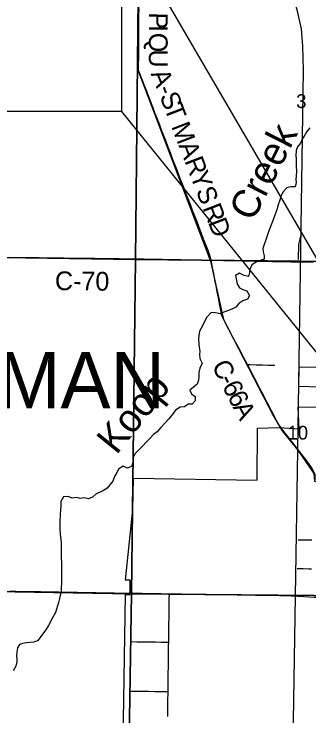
# Model space of a CAD drawing. Extents: x 0 to 34, y 0 to 22.
# Drawn here: x 4.43 to 5.324, y 17.068 to 19.194 of the extents above; entities that cross this region are included whole.
import ezdxf

# ---------------------------------------------------------------- set-up
doc = ezdxf.new("R2010")
doc.units = 0
for name, color, linetype in [('GM_X_City_Street', 7, 'Continuous'), ('GM_X_Corporation', 7, 'Continuous'), ('GM_X_County_Road', 7, 'Continuous'), ('GM_X_County_Road_Text', 7, 'Continuous'), ('GM_X_Minor_River', 7, 'Continuous'), ('GM_X_Minor_River_Text', 7, 'Continuous'), ('GM_X_Rail_Line', 7, 'Continuous'), ('GM_X_Section_Text', 7, 'Continuous'), ('GM_X_State_Route', 7, 'Continuous'), ('GM_X_Township_Road', 7, 'Continuous'), ('GM_X_Township_Text', 7, 'Continuous'), ('SH_Text', 7, 'Continuous')]:
    doc.layers.add(name, color=color, linetype=linetype)

msp = doc.modelspace()

# ---------------------------------------------------------------- linework, layer by layer
at = {"layer": 'GM_X_City_Street'}
for points in [[(5.2912, 17.6018), (5.3098, 17.6015), (5.325, 17.6013), (5.332, 17.6012)], [(5.288, 17.5145), (5.3067, 17.5143), (5.3233, 17.514), (5.3311, 17.5139)], [(4.8958, 17.0663), (4.8961, 17.085), (4.8963, 17.1036), (4.8966, 17.1223), (4.8967, 17.132), (4.8968, 17.1418), (4.8971, 17.1604), (4.8973, 17.1791), (4.8976, 17.1977), (4.8978, 17.2163), (4.8981, 17.235), (4.8983, 17.2536), (4.8985, 17.2723), (4.8987, 17.2818), (4.8988, 17.2914), (4.8991, 17.31), (4.8993, 17.3287), (4.8995, 17.3473), (4.8998, 17.366), (4.9, 17.3846), (4.9003, 17.4033), (4.9004, 17.4132), (4.9006, 17.4231), (4.9008, 17.4382)], [(4.7838, 17.2931), (4.8025, 17.2928), (4.8211, 17.2925), (4.8398, 17.2923), (4.8584, 17.292), (4.8758, 17.2917), (4.8931, 17.2915), (4.8988, 17.2914)], [(4.7819, 17.1435), (4.8005, 17.1432), (4.8191, 17.1429), (4.8378, 17.1426), (4.8564, 17.1424), (4.8724, 17.1421), (4.8884, 17.1419), (4.8968, 17.1418)]]:
    msp.add_lwpolyline(points, dxfattribs=at)
at = {"layer": 'GM_X_Corporation'}
for points in [[(4.7562, 19.4462), (4.7881, 19.4457), (4.8082, 19.4446), (4.7982, 18.4503), (3.7969, 18.4658), (3.7979, 18.8986)], [(5.3571, 18.0637), (5.2933, 18.0661), (5.2945, 18.1254), (5.6481, 18.1185)], [(4.7597, 16.9291), (4.7677, 17.4357), (4.7819, 17.4354), (4.7818, 17.4793), (4.7676, 17.4795), (4.7903, 17.6936), (4.7921, 17.7885), (5.1664, 17.7823), (5.168, 17.9398), (5.2337, 17.9415), (5.2939, 17.9379), (5.2911, 18.0031), (5.3565, 18.004)]]:
    msp.add_lwpolyline(points, dxfattribs=at)
for points in [[(5.8008, 19.4289), (5.7966, 18.4409), (4.7982, 18.4503), (4.8082, 19.4446)], [(3.7969, 18.4658), (4.7982, 18.4503), (4.7862, 17.4375), (3.785, 17.4549)], [(5.7966, 18.4409), (5.7831, 17.4286), (4.7862, 17.4375), (4.7982, 18.4503)], [(4.7862, 17.4375), (4.7695, 16.4317), (3.7672, 16.4521), (3.785, 17.4549)], [(4.7862, 17.4375), (5.7831, 17.4286), (5.7675, 16.4186), (4.7695, 16.4317)]]:
    msp.add_lwpolyline(points, close=True, dxfattribs=at)
at = {"layer": 'GM_X_County_Road'}
for points in [[(5.0579, 18.2907), (5.0565, 18.2978), (5.0529, 18.3161), (5.0494, 18.3344), (5.0458, 18.3527), (5.0422, 18.371), (5.0386, 18.3893), (5.0351, 18.4076), (5.0315, 18.4259), (5.0293, 18.4371), (5.0271, 18.4484), (5.0248, 18.46), (5.0181, 18.4774), (5.0114, 18.4948), (5.0047, 18.5122), (4.998, 18.5296), (4.9913, 18.547), (4.9846, 18.5644), (4.9779, 18.5818), (4.9712, 18.5992), (4.9645, 18.6166), (4.9578, 18.634), (4.9511, 18.6514), (4.9443, 18.6688), (4.9376, 18.6861), (4.9309, 18.7035), (4.9242, 18.7209), (4.9175, 18.7383), (4.9108, 18.7557), (4.9041, 18.7731), (4.8974, 18.7905), (4.8907, 18.8079), (4.884, 18.8253), (4.8773, 18.8427), (4.8706, 18.8601), (4.8639, 18.8775), (4.8572, 18.8949), (4.8505, 18.9122), (4.8438, 18.9296), (4.8384, 18.9435), (4.8331, 18.9574), (4.8264, 18.9748), (4.8197, 18.9922), (4.8137, 19.0079), (4.8077, 19.0236), (4.8078, 19.0422), (4.8079, 19.0609), (4.808, 19.0795), (4.8082, 19.0981), (4.8083, 19.1168), (4.8084, 19.1354), (4.8085, 19.1541), (4.8087, 19.1727), (4.8088, 19.1913), (4.8089, 19.21)], [(4.4131, 18.4573), (4.4317, 18.457), (4.4504, 18.4568), (4.469, 18.4566), (4.4876, 18.4564), (4.5063, 18.4561), (4.5249, 18.4559), (4.5436, 18.4557), (4.5622, 18.4555), (4.5808, 18.4552), (4.5995, 18.455), (4.6181, 18.4548), (4.6368, 18.4546), (4.6554, 18.4543), (4.6741, 18.4541), (4.6927, 18.4539), (4.7113, 18.4537), (4.73, 18.4534), (4.7486, 18.4532), (4.7673, 18.453), (4.7859, 18.4528), (4.7954, 18.4526), (4.8049, 18.4525), (4.8235, 18.4522), (4.8421, 18.4518), (4.8608, 18.4515), (4.8794, 18.4511), (4.898, 18.4508), (4.9167, 18.4504), (4.9353, 18.4501), (4.9539, 18.4497), (4.9726, 18.4494), (4.9912, 18.4491), (5.0091, 18.4487), (5.0271, 18.4484)], [(5.0271, 18.4484), (5.0457, 18.448), (5.0644, 18.4477), (5.083, 18.4473), (5.1016, 18.447), (5.1203, 18.4466), (5.1389, 18.4463), (5.1575, 18.4459), (5.1732, 18.4457)], [(5.1732, 18.4457), (5.1762, 18.4456), (5.1948, 18.4453), (5.2134, 18.4449), (5.2321, 18.4446), (5.2507, 18.4442), (5.2693, 18.4439), (5.285, 18.4436), (5.3007, 18.4433), (5.3194, 18.4432), (5.338, 18.443)], [(5.2404, 17.9399), (5.2305, 17.9528), (5.2249, 17.964), (5.2193, 17.9752), (5.2106, 17.9917), (5.202, 18.0082), (5.1934, 18.0248), (5.1848, 18.0413), (5.1761, 18.0578), (5.1675, 18.0743), (5.1625, 18.084), (5.1574, 18.0936), (5.149, 18.1102), (5.1434, 18.1212), (5.1377, 18.1323), (5.1356, 18.1365), (5.1268, 18.1529), (5.118, 18.1693), (5.1092, 18.1858), (5.1014, 18.2004), (5.0935, 18.215), (5.0849, 18.2315), (5.0764, 18.2481), (5.0682, 18.2638), (5.0601, 18.2795), (5.0579, 18.2907)], [(5.3424, 17.7822), (5.3424, 17.798), (5.3356, 17.8137), (5.3302, 17.8221), (5.3248, 17.8305), (5.3134, 17.8453), (5.302, 17.86), (5.2961, 17.8678), (5.2901, 17.8755), (5.2787, 17.8903), (5.2673, 17.905), (5.2559, 17.9198), (5.2481, 17.9299), (5.2404, 17.9399)]]:
    msp.add_lwpolyline(points, dxfattribs=at)
at = {"layer": 'GM_X_Minor_River'}
for points in [[(5.3264, 18.8493), (5.3174, 18.8378), (5.3092, 18.8243), (5.3036, 18.8145), (5.2977, 18.8033), (5.2891, 18.7913), (5.285, 18.7808), (5.2839, 18.7656), (5.2845, 18.7561), (5.285, 18.7435), (5.2855, 18.7325), (5.2859, 18.7177), (5.2845, 18.704), (5.2842, 18.693), (5.2848, 18.6835), (5.2822, 18.6703), (5.2693, 18.6702), (5.2571, 18.6678), (5.2443, 18.654), (5.2387, 18.6409), (5.2354, 18.6299), (5.2309, 18.6163), (5.226, 18.6005), (5.2199, 18.5843), (5.2159, 18.5741), (5.2111, 18.5609), (5.2059, 18.5478), (5.201, 18.5338), (5.1961, 18.5195), (5.1929, 18.5097)], [(5.1929, 18.5097), (5.188, 18.4961), (5.1843, 18.484), (5.1849, 18.4741), (5.1876, 18.4615), (5.1882, 18.452), (5.1759, 18.4477), (5.1637, 18.4423), (5.151, 18.4342), (5.1446, 18.4207), (5.144, 18.4108), (5.1407, 18.3987), (5.1279, 18.4017), (5.1136, 18.4092), (5.101, 18.4023), (5.1065, 18.3771), (5.1134, 18.3644), (5.1231, 18.3596), (5.1352, 18.3559), (5.1436, 18.3417), (5.138, 18.33), (5.1231, 18.3254), (5.1108, 18.3169), (5.1018, 18.3057), (5.0922, 18.3006), (5.0796, 18.2964), (5.0655, 18.291), (5.0544, 18.2863), (5.0408, 18.2889), (5.0275, 18.29), (5.0147, 18.2758), (5.008, 18.2646), (5, 18.2476), (4.9925, 18.2337), (4.9896, 18.2201), (4.9893, 18.2091), (4.9901, 18.1942), (4.9914, 18.1847), (4.9934, 18.1725), (4.9925, 18.163), (4.9933, 18.1504), (5.0002, 18.1362), (4.9931, 18.1212), (4.9901, 18.1079), (4.9898, 18.095), (4.9892, 18.0855), (4.9848, 18.0734), (4.9744, 18.0638), (4.9628, 18.0549), (4.9682, 18.0438), (4.9794, 18.0355), (4.9791, 18.0222), (4.9698, 18.0122), (4.9573, 18.0125), (4.9469, 18.0047), (4.9336, 18.0035), (4.9197, 17.9939), (4.9088, 17.9805), (4.8983, 17.9666), (4.8882, 17.9558), (4.8746, 17.9421), (4.8637, 17.929), (4.8532, 17.9201), (4.8424, 17.9097), (4.8315, 17.8986), (4.8191, 17.8855), (4.8086, 17.8744), (4.7974, 17.8625), (4.7914, 17.8508), (4.7904, 17.8375), (4.7867, 17.825), (4.7736, 17.8185), (4.7605, 17.8241), (4.7482, 17.8168), (4.7419, 17.8051), (4.7348, 17.7931), (4.7292, 17.7796), (4.7206, 17.7683), (4.7128, 17.7583), (4.7012, 17.7513), (4.6909, 17.7454), (4.679, 17.7412), (4.6678, 17.7311), (4.6555, 17.7257), (4.6423, 17.7291), (4.6309, 17.7263), (4.6204, 17.7299), (4.6067, 17.728), (4.5942, 17.7328), (4.5798, 17.7316), (4.5719, 17.7174), (4.572, 17.7056), (4.5713, 17.6919), (4.5695, 17.6782), (4.5691, 17.6577), (4.5685, 17.6463), (4.5686, 17.6334), (4.5698, 17.6189), (4.5711, 17.6093), (4.573, 17.5944), (4.5731, 17.58)], [(4.5731, 17.58), (4.5725, 17.5686), (4.5726, 17.556), (4.5731, 17.5465), (4.5739, 17.5316), (4.574, 17.5172), (4.5741, 17.5061), (4.5743, 17.4947), (4.5737, 17.4677), (4.5731, 17.4578), (4.5725, 17.4472), (4.5707, 17.4373), (4.5682, 17.4241), (4.5645, 17.4112), (4.5555, 17.3818), (4.5472, 17.3652), (4.5349, 17.3419), (4.527, 17.3292), (4.5169, 17.3157), (4.5095, 17.306), (4.5009, 17.2959), (4.489, 17.2916), (4.4795, 17.2903), (4.4681, 17.289), (4.4563, 17.2874), (4.4468, 17.2842), (4.4412, 17.2745), (4.4383, 17.2623), (4.4381, 17.2506), (4.439, 17.241), (4.4384, 17.2315), (4.4358, 17.2183), (4.428, 17.2051)]]:
    msp.add_lwpolyline(points, dxfattribs=at)
at = {"layer": 'GM_X_Rail_Line'}
msp.add_line((5.2889, 17.8736), (5.2896, 17.8726), dxfattribs=at)
for points in [[(4.7739, 20.9), (4.6919, 20.1583), (4.6938, 20.1236), (4.7468, 19.7618), (4.8037, 19.4528), (4.8092, 19.4143), (4.8049, 19.0246), (5.0256, 18.4453), (5.0645, 18.2691), (5.215, 17.9781), (5.2422, 17.9318), (5.2889, 17.8736)], [(5.2312, 14.404), (5.2346, 14.4124), (5.2368, 14.4226), (5.243, 14.9028), (5.2517, 15.4121), (5.2672, 16.4237), (5.283, 17.4313), (5.2899, 17.8728), (5.3076, 19.0241), (5.3057, 19.0962), (5.3011, 19.1491), (5.2883, 19.2066), (5.0953, 19.84), (5.0724, 19.9157), (5.0587, 19.9632), (5.0513, 20.0198), (5.0584, 20.4524), (5.0684, 20.9)], [(5.2919, 18.4509), (5.2932, 18.4955), (5.2963, 18.5082), (5.2999, 18.5253)], [(5.2896, 17.8726), (5.3382, 17.8025), (5.341, 17.7796), (5.4725, 17.777), (5.4714, 17.6262), (5.4707, 17.4295), (5.6005, 17.4236), (5.6403, 16.9891), (5.6877, 16.4369), (5.6901, 16.3801), (5.6782, 16.0923), (5.6866, 15.9567), (5.7169, 15.8341), (5.7394, 15.7967)]]:
    msp.add_lwpolyline(points, dxfattribs=at)
at = {"layer": 'GM_X_State_Route'}
msp.add_line((4.7868, 17.4398), (4.8003, 17.4396), dxfattribs=at)
for points in [[(4.417, 17.446), (4.4356, 17.4457), (4.4543, 17.4454), (4.4729, 17.4451), (4.4916, 17.4448), (4.5102, 17.4445), (4.5288, 17.4442), (4.5475, 17.4439), (4.5661, 17.4435), (4.5785, 17.4433)], [(4.5785, 17.4433), (4.5848, 17.4432), (4.6034, 17.4429), (4.622, 17.4426), (4.6407, 17.4423), (4.6593, 17.442), (4.678, 17.4417), (4.6966, 17.4413), (4.7152, 17.441), (4.7339, 17.4407), (4.7525, 17.4404), (4.7692, 17.4401), (4.7858, 17.4398), (4.7868, 17.4398)], [(4.8003, 17.4396), (4.8189, 17.4394), (4.8376, 17.4391), (4.8562, 17.4388), (4.8748, 17.4385), (4.8878, 17.4383), (4.9008, 17.4382), (4.9194, 17.4379), (4.938, 17.4376), (4.9567, 17.4373), (4.9753, 17.4371), (4.994, 17.4368), (5.0087, 17.4366)], [(5.0087, 17.4366), (5.0126, 17.4365), (5.0312, 17.4362), (5.0499, 17.436), (5.0685, 17.4357), (5.0872, 17.4354), (5.1058, 17.4351), (5.1244, 17.4349), (5.1431, 17.4346), (5.1617, 17.4343), (5.1804, 17.4341), (5.199, 17.4338), (5.2177, 17.4335), (5.2352, 17.4333), (5.2527, 17.433), (5.2713, 17.4319), (5.2899, 17.4309), (5.2987, 17.4304)], [(5.2987, 17.4304), (5.3085, 17.4298), (5.3236, 17.429), (5.3388, 17.4281), (5.3574, 17.4279), (5.3761, 17.4277), (5.3905, 17.4275), (5.4049, 17.4273)]]:
    msp.add_lwpolyline(points, dxfattribs=at)
at = {"layer": 'GM_X_Township_Road'}
msp.add_lwpolyline([(5.1377, 18.1323), (5.1456, 18.1321), (5.1642, 18.1317), (5.1828, 18.1312), (5.1992, 18.1308), (5.2155, 18.1305), (5.2204, 18.1303)], dxfattribs=at)
at = {"layer": 'SH_Text'}
for points in [[(2.7075, 19.4692), (4.7562, 19.4692), (4.7562, 18.8986), (2.7075, 18.8986)], [(5.9461, 17.427), (4.7562, 19.4692), (4.7562, 18.8986)]]:
    msp.add_lwpolyline(points, close=True, dxfattribs=at)

# ---------------------------------------------------------------- texts
at = {"layer": 'GM_X_County_Road_Text'}
for s, height, rotation, p in [('P', 0.0568, 269.7078, (4.8393, 19.1989)), ('I', 0.0568, 269.7073, (4.8391, 19.1605)), ('Q', 0.0568, 269.7137, (4.839, 19.1372)), ('U', 0.0568, 270.1276, (4.8387, 19.0867)), ('A', 0.0568, 292.183, (4.8435, 19.0135)), ('-', 0.0568, 290.9918, (4.8622, 18.9675)), ('S', 0.0568, 290.9979, (4.8706, 18.9457)), ('T', 0.0568, 290.9944, (4.8843, 18.9099)), ('M', 0.0568, 290.9954, (4.9058, 18.8539)), ('A', 0.0568, 290.995, (4.9279, 18.7963)), ('R', 0.0568, 290.996, (4.9458, 18.7496)), ('Y', 0.0568, 290.9971, (4.9625, 18.706)), ('S', 0.0568, 290.9954, (4.9805, 18.6594)), ('R', 0.0568, 290.996, (5.0005, 18.6072)), ('D', 0.0568, 290.9954, (5.0172, 18.5637)), ('C-70', 0.05682, 359.3142, (4.5539, 18.3579)), ('C', 0.0568, 296.8243, (5.028, 18.1293)), ('-', 0.0568, 296.843, (5.0491, 18.0876)), ('6', 0.0568, 296.8981, (5.0596, 18.0668)), ('6', 0.0568, 297.087, (5.0755, 18.0354)), ('A', 0.0568, 297.8395, (5.0919, 18.0035))]:
    msp.add_text(s, height=height, rotation=rotation, dxfattribs=at).set_placement(p)
at = {"layer": 'GM_X_Minor_River_Text'}
for s, rotation, p in [('Creek', 63.05, (5.1538, 18.5623)), ('Koop', 51.0974, (4.7404, 17.8565))]:
    msp.add_text(s, height=0.08523, rotation=rotation, dxfattribs=at).set_placement(p)
at = {"layer": 'GM_X_Section_Text'}
for s, height, p in [('3', 0.0419, (5.2851, 18.9092)), ('10', 0.04186, (5.2589, 17.905))]:
    msp.add_text(s, height=height, rotation=0, dxfattribs=at).set_placement(p)
at = {"layer": 'GM_X_Township_Text'}
msp.add_text('GERMAN', height=0.17045, rotation=0, dxfattribs=at).set_placement((3.8869, 17.9996))

doc.saveas('drawing.dxf')
